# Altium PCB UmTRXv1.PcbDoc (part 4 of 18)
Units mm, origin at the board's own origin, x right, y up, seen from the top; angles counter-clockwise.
Board outline 172 x 113 mm, 6 copper layers (Top Layer, GND, MidLayer1, Mid-Layer 2, InternalPlane2, Bottom Layer); 766 components, 613 nets, 3008 pads, 1360 vias.
Unrouted connection lines stored in the file: 2.
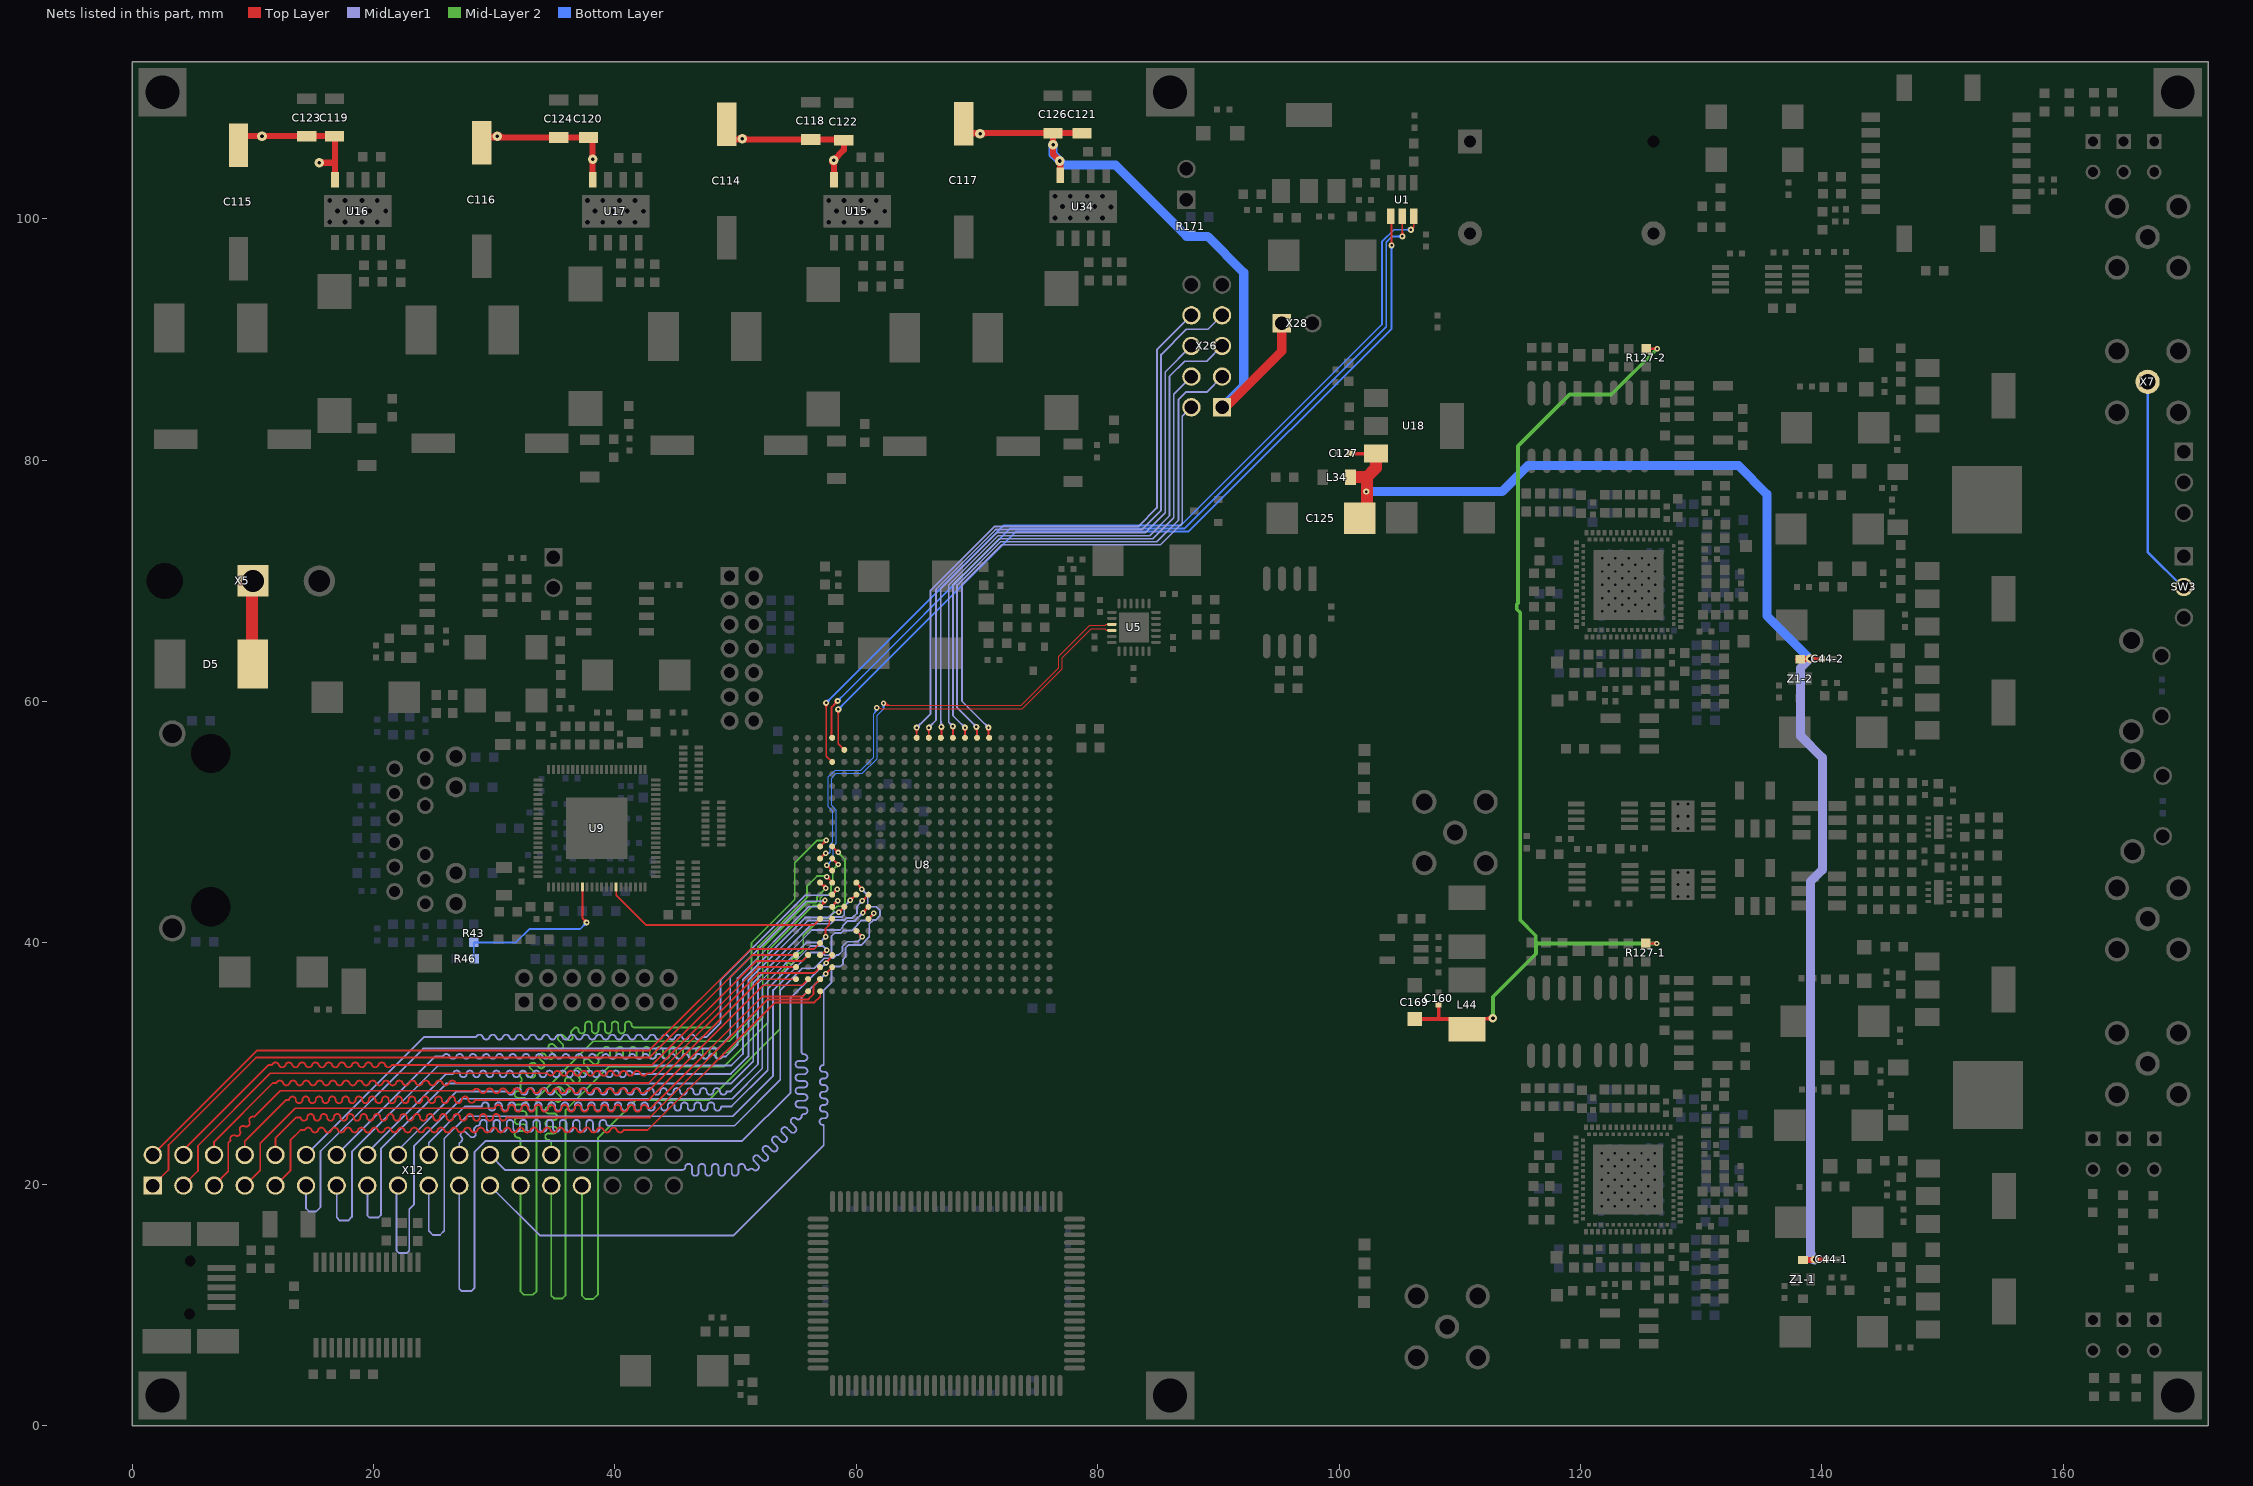
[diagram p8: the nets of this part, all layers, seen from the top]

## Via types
v1: diameter 0.45, hole 0.2, Top Layer to Bottom Layer, tented both sides, 554 vias
v2: diameter 0.5, hole 0.2, Top Layer to Bottom Layer, tented both sides, 468 vias
v3: diameter 0.7, hole 0.3, Top Layer to Bottom Layer, tented both sides, 206 vias
v4: diameter 0.4, hole 0.2, Top Layer to Bottom Layer, tented both sides, 82 vias
v5: diameter 0.8, hole 0.3, Top Layer to Bottom Layer, tented both sides, 16 vias
v6: diameter 0.6, hole 0.25, Top Layer to Bottom Layer, tented both sides, 16 vias
v7: diameter 0.5, hole 0.3, Top Layer to Bottom Layer, tented both sides, 8 vias
v8: diameter 0.7, hole 0.3, Top Layer to Bottom Layer, 4 vias
v9: diameter 0.6, hole 0.3, Top Layer to Bottom Layer, tented both sides, 4 vias
v10: diameter 0.5, hole 0.2, Top Layer to Bottom Layer, 2 vias

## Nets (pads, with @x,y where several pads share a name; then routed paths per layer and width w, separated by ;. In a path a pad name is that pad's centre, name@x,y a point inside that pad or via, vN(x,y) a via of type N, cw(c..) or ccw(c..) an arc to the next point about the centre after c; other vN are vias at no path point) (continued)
+6.5V: C44-1.1 C44-2.1 C125.1 C127.1 L34.2 U18.3 Z1-1.1 Z1-2.1 | length 118
  Top Layer w0.3: C127.1@100.9,80.6 100.95,80.55 U18.3@103.05,80.55 ; v3(139.015,63.567) 139.931,63.567 C44-2.1@139.94,63.576 ; v3@139.157,63.426 cw(c139.498,63.084) 139.498,63.567 cw(c139.498,64.05) v3@139.157,63.708 ; v3(139.415,13.772) 140.331,13.772 C44-1.1@140.34,13.781 ; v3@139.557,13.63 cw(c139.898,13.289) 139.898,13.772 cw(c139.898,14.254) v3@139.557,13.913
  Top Layer w0.5: U18.3@102.95,80.45 U18.3@103.05,80.55 ; Z1-2.1@138.04,63.526 138.975,63.526 v3(139.015,63.567) ; Z1-1.1@138.44,13.731 139.375,13.731 v3(139.415,13.772)
  Top Layer w1: L34.2@100.95,78.6 102.3,78.6 ; C125.1@101.7,75.2 102.3,75.8 102.3,78.6 ; U18.3@103.05,80.55 103.05,79.35 102.3,78.6
  MidLayer1 w0.75: v3(139.015,63.567) 138.25,62.802 138.25,57.15 140.05,55.35 140.05,46.066 139.05,45.066 139.05,14.137 ; 139.05,14.593 ccw(c140.237,14.593) v3@139.398,13.754 ; v3@139.414,13.747 cw(c139.441,14.137) 139.05,14.137 ; v3(139.415,13.772) 139.05,14.137
  Bottom Layer w0.75: v2(102.25,77.4) 113.5,77.4 115.65,79.55 133.1,79.55 135.45,77.2 135.45,67.132 v3(139.015,63.567)
+12V: C114.1 C115.1 C116.1 C117.1 C118.1 C119.1 C120.1 C121.1 C122.1 C123.1 C124.1 C126.1 D5.2 R171.1 U15.8 U16.8 U17.8 U34.8 X5.1 X26.1 X28.1 | length 102.4
  Top Layer w0.5: C115.1@9.55,106.85 v5(10.75,106.85) C123.1@14.45,106.85 C119.1@16.75,106.85 16.795,106.805 16.795,104.55 ; v5(15.5,104.65) 16.695,104.65 16.795,104.55 ; U16.8@16.795,103.305 16.795,104.55 ; C116.1@29.4,106.75 C120.1@37.8,106.75 ; C116.1@29.646,106.75 ccw(c29.646,107.454) v5@30.144,106.956 ; v5@30.356,106.956 ccw(c30.854,107.454) 30.854,106.75 ; U17.8@38.153,103.239 C120.1@38.153,106.397 ; C114.1@49.582,106.568 C118.1@56.215,106.568 58.915,106.568 C122.1@58.965,106.518 58.965,105.718 v5(58.115,104.868) ; C114.1@49.99,106.568 ccw(c49.99,107.21) v5@50.444,106.756 ; v5@50.656,106.756 ccw(c51.11,107.21) 51.11,106.568 ; v5@57.965,104.718 v5(58.115,104.868) ; v5@58.009,104.762 cw(c57.709,104.462) 58.133,104.462 ; U15.8@58.133,103.289 58.133,104.85 v5(58.115,104.868) ; C117.1@69,107.1 C126.1@76.3,107.1 ; 69.767,107.1 cw(c69.767,106.567) v5@70.144,106.944 ; v5@70.356,106.944 cw(c70.733,106.567) 70.733,107.1 ; v5@76.744,104.694 cw(c76.384,104.334) 76.893,104.334 ; U34.8@76.893,103.602 76.893,104.757 v5(76.85,104.8) 76.3,105.35 v5(76.3,106.15) C126.1@76.3,107.1 ; C121.1@78.35,107.1 C126.1@76.3,107.1
  Top Layer w0.75: X26.1@90.3,84.39 90.59,84.39 95.25,89.05 X28.1@95.25,91.55
  Top Layer w1: D5.2@9.929,63.15 X5.1@9.929,70
  Bottom Layer w0.75: v5(76.3,106.15) 76.3,105.35 v5(76.85,104.8) 77.2,104.45 81.475,104.45 87.375,98.55 89.1,98.55 92.1,95.55 92.1,86.19 X26.1@90.3,84.39
  other v5: 38.15,104.95 50.55,106.65 30.25,106.85 70.25,107.05
-5V: C160.1 C169.1 L44.2 R127-1.2 R127-2.2 | length 86.6
  Top Layer w0.2: R127-1.2@125.411,39.958 126.315,39.958 v1(126.318,39.955) ; R127-2.2@125.45,89.25 126.354,89.25 v1(126.357,89.247) ; 126.008,39.958 cw(c126.008,39.645) v1@126.23,39.866 ; 126.025,39.958 ccw(c126.025,40.248) v1@126.23,40.043 ; 126.047,89.25 cw(c126.047,88.936) v1@126.269,89.158 ; 126.064,89.25 ccw(c126.064,89.54) v1@126.269,89.335
  Top Layer w0.3: C169.1@106.25,33.7 108.2,33.7 ; C160.1@108.25,34.9 108.25,33.75 108.2,33.7 ; 112.19,33.718 ccw(c112.19,34.31) v3@112.609,33.891 ; 112.344,33.718 cw(c112.344,33.344) v3@112.609,33.609 ; v3@112.75,33.7 112.732,33.718 110.55,33.718 110.532,33.7 108.2,33.7
  Mid-Layer 2 w0.3: v3@112.609,33.891 ccw(c112.267,34.233) 112.75,34.233 ccw(c113.233,34.233) v3@112.891,33.891 ; v3(112.75,33.75) 112.75,35.55 116.319,39.119 116.319,39.955 ; 116.319,40.096 116.319,39.955 ; v1(126.318,39.955) 116.319,39.955 ; v1(126.357,89.247) 122.561,85.45 119.1,85.45 114.825,81.175 114.825,68.147 114.725,68.047 114.725,67.653 115,67.378 115,41.9 116.3,40.6 116.3,39.955 116.319,39.955
ACT_LED: R43.2 R46.1 U9.50 | length 15.8
  Top Layer w0.15: U9.50@37.3,44.625 37.3,42.05 v2(37.65,41.7) ; v2@37.475,41.7 ccw(c37.053,41.7) 37.351,41.999 ccw(c37.65,42.297) v2@37.65,41.875
  Bottom Layer w0.15: R46.1@28.35,38.7 28.3,38.75 R43.2@28.3,40.05 31.8,40.05 32.9,41.15 37.1,41.15 v2(37.65,41.7) ; v2@37.475,41.7 cw(c37.053,41.7) 37.351,41.401 cw(c37.65,41.103) v2@37.65,41.525
AUX1: U8.AB6 X26.2 | length 45.2
  Top Layer w0.15: v2@70.826,57.726 cw(c70.528,57.428) 70.95,57.428 cw(c71.372,57.428) v2@71.074,57.726 ; v2(70.95,57.85) 70.95,57.05 U8.AB6@71,57
  MidLayer1 w0.15: v2@70.775,57.85 ccw(c70.353,57.85) 70.651,58.149 ccw(c70.95,58.447) v2@70.95,58.025 ; v2(70.95,57.85) 68.75,60.05 68.75,69.7 72.05,73 85.2,73 87,74.8 87,83.63 X26.2@87.76,84.39
AUX2: U8.AB7 X26.3 | length 49.6
  Top Layer w0.15: v2@69.826,57.776 cw(c69.407,57.357) 70,57.357 ; v2(69.95,57.9) 70,57.85 U8.AB7@70,57 ; 70,57.598 cw(c70.252,57.598) v2@70.074,57.776
  MidLayer1 w0.15: v2@69.775,57.9 ccw(c69.353,57.9) 69.651,58.199 ccw(c69.95,58.497) v2@69.95,58.075 ; v2(69.95,57.9) 68.35,59.5 68.35,69.654 71.946,73.25 84.9,73.25 86.7,75.05 86.7,85.05 87.3,85.65 89.02,85.65 X26.3@90.3,86.93
AUX3: U8.AB8 X26.4 | length 47.3
  Top Layer w0.15: v2@68.876,57.726 cw(c68.578,57.428) 69,57.428 cw(c69.422,57.428) v2@69.124,57.726 ; U8.AB8@69,57 v2(69,57.85)
  MidLayer1 w0.15: v2@68.825,57.85 ccw(c68.403,57.85) 68.701,58.149 ccw(c69,58.447) v2@69,58.025 ; v2(69,57.85) 68,58.85 68,69.657 71.843,73.5 84.55,73.5 86.3,75.25 86.3,85.47 X26.4@87.76,86.93
AUX4: U8.AB9 X26.5 | length 51.8
  Top Layer w0.15: v2@67.876,57.826 cw(c67.578,57.528) 68,57.528 cw(c68.422,57.528) v2@68.124,57.826 ; U8.AB9@68,57 v2(68,57.95)
  MidLayer1 w0.15: v2@67.825,57.95 ccw(c67.403,57.95) 67.701,58.249 ccw(c68,58.547) v2@68,58.125 ; v2(68,57.95) 67.65,58.3 67.65,69.661 71.739,73.75 84.3,73.75 85.95,75.4 85.95,86.95 87.2,88.2 89.03,88.2 X26.5@90.3,89.47
AUX5: U8.AB10 X26.6 | length 49.7
  Top Layer w0.15: v2@66.926,57.776 cw(c66.628,57.478) 67.05,57.478 cw(c67.472,57.478) v2@67.174,57.776 ; U8.AB10@67,57 67.05,57.05 v2(67.05,57.9)
  MidLayer1 w0.15: v2@66.926,58.024 ccw(c66.748,58.202) 67,58.202 ; 67,58.443 ccw(c67.593,58.443) v2@67.174,58.024 ; v2(67.05,57.9) 67,57.9 66.95,57.95 67,58 67,69.364 71.636,74 83.95,74 85.6,75.65 85.6,87.31 X26.6@87.76,89.47
AUX6: U8.AB11 X26.7 | length 54.5
  Top Layer w0.15: v2@65.876,57.726 cw(c65.578,57.428) 66,57.428 cw(c66.422,57.428) v2@66.124,57.726 ; U8.AB11@66,57.05 v2(66,57.85)
  MidLayer1 w0.15: v2(66,57.85) 66.6,58.45 66.6,69.318 71.532,74.25 83.65,74.25 85.25,75.85 85.25,88.75 87.35,90.85 89.14,90.85 X26.7@90.3,92.01 ; v2@66,58.025 ccw(c66,58.447) 66.299,58.149 ccw(c66.597,57.85) v2@66.175,57.85
AUX7: U8.AB12 X26.8 | length 52.7
  Top Layer w0.15: v2@64.876,57.726 cw(c64.578,57.428) 65,57.428 cw(c65.422,57.428) v2@65.124,57.726 ; U8.AB12@65,57 v2(65,57.85)
  MidLayer1 w0.15: v2(65,57.85) 66.15,59 66.15,69.221 71.429,74.5 83.35,74.5 84.9,76.05 84.9,89.15 X26.8@87.76,92.01 ; v2@65,58.025 ccw(c65,58.447) 65.299,58.149 ccw(c65.597,57.85) v2@65.175,57.85
CLK_FPGA_N: U5.9 U8.L19 | length 43.4
  Top Layer w0.1: v1@62.232,59.832 ccw(c62.552,60.152) 62.552,59.7 ; v1(62.25,59.85) 62.4,59.7 73.65,59.7 76.77,62.82 76.77,63.754 79.334,66.318 80.3,66.318 80.617,66.318 80.7,66.4 U5.9@81.175,66.4 ; v1@62.303,59.903 ccw(c62.793,60.393) 62.793,59.7 ; v1@62.374,59.974 ccw(c63.035,60.635) 63.035,59.7
  Top Layer w0.15: v1@57.55,46.3 cw(c57.55,45.938) 57.806,46.194 cw(c58.062,46.45) v1@57.7,46.45 ; v1(57.55,46.45) U8.L19@58,46
  Bottom Layer w0.1: v1(57.55,46.45) 58.1,47 58.1,48.05 58.33,48.28 58.33,51.016 57.95,51.396 57.95,53.65 58.35,54.05 60.5,54.05 61.73,55.28 61.73,58.88 62.25,59.4 v1(62.25,59.85) ; v1@57.55,46.625 ccw(c57.55,47.047) 57.849,46.749 ccw(c58.147,46.45) v1@57.725,46.45 ; v1@62.126,59.726 cw(c61.828,59.428) 62.25,59.428 cw(c62.672,59.428) v1@62.374,59.726
CLK_FPGA_P: U5.10 U8.M20 | length 41.4
  Top Layer w0.1: v1(61.7,59.5) 61.75,59.55 61.85,59.55 62.005,59.395 62.495,59.395 62.52,59.42 73.766,59.42 77.05,62.704 77.05,63.638 79.45,66.038 80.562,66.038 80.7,65.9 U5.10@81.175,65.9
  Top Layer w0.15: U8.M20@57,47 v1(57.45,47.45) ; v1@57.3,47.45 cw(c56.938,47.45) 57.194,47.194 cw(c57.45,46.938) v1@57.45,47.3
  Bottom Layer w0.1: v1(57.45,47.45) 57.75,47.45 ; v1@57.602,47.364 cw(c57.75,47.28) 57.75,47.45 ; v1@57.602,47.536 ccw(c57.75,47.62) 57.75,47.45 ; v1@61.538,59.434 cw(c61.167,59.283) 61.45,59 ; 61.557,59.107 ccw(c61.318,59.345) v1@61.63,59.472 ; v1@61.64,59.335 cw(c61.609,59.25) 61.7,59.25 ; 61.663,59.213 ccw(c61.47,59.406) v1@61.723,59.509 ; v1(61.7,59.5) 61.7,59.25 ; v1@61.76,59.335 ccw(c61.791,59.25) 61.7,59.25 ; 57.75,47.45 57.82,47.52 57.82,48.166 58.05,48.396 58.05,50.9 57.67,51.28 57.67,53.766 58.152,54.248 58.234,54.33 60.384,54.33 61.45,55.396 61.45,59 ; 61.45,59 61.7,59.25
CLK_TO_MAC: U8.G20 U9.57 | length 18.8
  Top Layer w0.15: U9.57@40.1,44.625 40.1,43.95 42.55,41.5 56.5,41.5 U8.G20@57,42
CLKIO: SW3.2 X7.1 | length 18.3
  Bottom Layer w0.2: X7.1@167,86.5 167,72.4 SW3.2@169.95,69.45
DAC_CLK: U1.5 U8.AB19 | length 74.4
  Top Layer w0.15: U8.AB19@57.95,57 57.95,59.55 v2(58.45,60.05) ; v2@58.275,60.05 cw(c57.853,60.05) 58.151,59.751 cw(c58.45,59.453) v2@58.45,59.875 ; v2@105.126,98.674 ccw(c104.855,98.945) 105.239,98.945 ; 105.239,99 ccw(c105.7,99) v2@105.374,98.674 ; U1.5@105.239,100.215 105.239,98.561 v2(105.25,98.55)
  Bottom Layer w0.15: v2(58.45,60.05) 72.75,74.35 87.2,74.35 103.9,91.05 103.9,98.05 104.4,98.55 v2(105.25,98.55) ; v2@58.45,60.225 ccw(c58.45,60.647) 58.749,60.349 ccw(c59.047,60.05) v2@58.625,60.05 ; v2@105.126,98.426 ccw(c104.828,98.128) 104.828,98.55 ccw(c104.828,98.972) v2@105.126,98.674
DAC_DIN: U1.4 U8.AA18 | length 74.5
  Top Layer w0.15: v2@58.376,59.226 cw(c58.078,58.928) 58.5,58.928 cw(c58.922,58.928) v2@58.624,59.226 ; v2(58.5,59.35) 58.5,56.5 U8.AA18@59,56 ; v2@104.226,97.924 ccw(c103.928,98.222) 104.35,98.222 ccw(c104.772,98.222) v2@104.474,97.924 ; U1.4@104.288,100.215 104.35,100.153 v2(104.35,97.8)
  Bottom Layer w0.15: v2(58.5,59.35) 73.25,74.1 87.55,74.1 104.35,90.9 v2(104.35,97.8) ; v2@58.5,59.525 ccw(c58.5,59.947) 58.799,59.649 ccw(c59.097,59.35) v2@58.675,59.35 ; v2@104.226,97.676 cw(c103.928,97.378) 104.35,97.378 cw(c104.772,97.378) v2@104.474,97.676
DAC_NSY: U1.6 U8.Y19 | length 77.5
  Top Layer w0.15: v2@57.376,59.776 cw(c57.078,59.478) 57.5,59.478 cw(c57.922,59.478) v2@57.624,59.776 ; v2(57.5,59.9) 57.5,55.488 U8.Y19@57.994,54.994 ; v2(105.95,99.1) 106.19,99.34 ; v2@105.979,99.273 ccw(c106.019,99.51) 106.19,99.34 ; v2@106.123,99.129 cw(c106.36,99.169) 106.19,99.34 ; U1.6@106.19,100.215 106.19,99.34
  Bottom Layer w0.15: v2(57.5,59.9) 72.2,74.6 86.9,74.6 103.55,91.25 103.55,98.1 104.55,99.1 v2(105.95,99.1) ; v2@57.5,60.075 ccw(c57.5,60.497) 57.799,60.199 ccw(c58.097,59.9) v2@57.675,59.9 ; v2@105.826,98.976 ccw(c105.528,98.678) 105.528,99.1 ccw(c105.528,99.522) v2@105.826,99.224
DEBUG0: U8.D22 X12.1 | length 62.4
  Top Layer w0.15: X12.1@1.7,19.9 3,21.2 3,23.25 10.25,30.5 42.85,30.5 51.35,39 U8.D22@55,39
DEBUG1: U8.E20 X12.2 | length 62.6
  Top Layer w0.15: X12.2@1.7,22.44 10.36,31.1 42.85,31.1 51.25,39.5 56.5,39.5 U8.E20@57,40
DEBUG2: U8.C22 X12.3 | length 62.1
  Top Layer w0.15: X12.3@4.24,19.9 5.45,21.11 5.45,23.2 11.45,29.2 34.4,29.2 ccw(c34.675,29.327) 34.95,29.2 cw(c35.225,29.111) 35.5,29.2 ccw(c35.775,29.289) 36.05,29.2 cw(c36.325,29.111) 36.6,29.2 ccw(c36.875,29.289) 37.15,29.2 cw(c37.425,29.111) 37.7,29.2 ccw(c37.975,29.289) 38.25,29.2 cw(c38.525,29.111) 38.8,29.2 ccw(c39.075,29.289) 39.35,29.2 cw(c39.625,29.111) 39.9,29.2 ccw(c40.175,29.289) 40.45,29.2 cw(c40.725,29.111) 41,29.2 ccw(c41.275,29.289) 41.55,29.2 cw(c41.825,29.111) 42.1,29.2 ccw(c42.375,29.289) 42.65,29.2 43.05,29.2 51.85,38 U8.C22@55,38
DEBUG3: U8.D21 X12.4 | length 62
  Top Layer w0.15: X12.4@4.24,22.44 4.24,22.84 11.3,29.9 11.6,29.9 cw(c11.875,29.811) 12.15,29.9 ccw(c12.425,29.989) 12.7,29.9 cw(c12.975,29.811) 13.25,29.9 ccw(c13.525,29.989) 13.8,29.9 cw(c14.075,29.811) 14.35,29.9 ccw(c14.625,29.989) 14.9,29.9 cw(c15.175,29.811) 15.45,29.9 ccw(c15.725,29.989) 16,29.9 cw(c16.275,29.811) 16.55,29.9 ccw(c16.825,29.989) 17.1,29.9 cw(c17.375,29.811) 17.65,29.9 ccw(c17.925,29.989) 18.2,29.9 cw(c18.475,29.811) 18.75,29.9 ccw(c19.025,29.989) 19.3,29.9 cw(c19.575,29.811) 19.85,29.9 ccw(c20.125,29.989) 20.4,29.9 cw(c20.675,29.811) 20.95,29.9 ccw(c21.225,29.989) 21.5,29.9 43.1,29.9 51.7,38.5 55.5,38.5 U8.D21@56,39
DEBUG4: U8.B22 X12.5 | length 62.1
  Top Layer w0.15: X12.5@6.78,19.9 7.95,21.07 7.95,23.45 8.15,23.65 cw(c8.407,23.781) 8.539,24.039 ccw(c8.67,24.296) 8.928,24.428 cw(c9.185,24.559) 9.317,24.817 ccw(c9.448,25.074) 9.706,25.206 cw(c9.989,25.312) 10.095,25.595 12.25,27.75 28.25,27.75 cw(c28.525,27.607) 28.8,27.75 ccw(c29.075,27.839) 29.35,27.75 cw(c29.625,27.661) 29.9,27.75 ccw(c30.175,27.839) 30.45,27.75 cw(c30.725,27.661) 31,27.75 ccw(c31.275,27.839) 31.55,27.75 cw(c31.825,27.661) 32.1,27.75 ccw(c32.375,27.839) 32.65,27.75 cw(c32.925,27.661) 33.2,27.75 ccw(c33.475,27.839) 33.75,27.75 cw(c34.025,27.661) 34.3,27.75 ccw(c34.575,27.839) 34.85,27.75 cw(c35.125,27.661) 35.4,27.75 ccw(c35.675,27.839) 35.95,27.75 cw(c36.225,27.661) 36.5,27.75 ccw(c36.775,27.839) 37.05,27.75 cw(c37.325,27.661) 37.6,27.75 ccw(c37.875,27.839) 38.15,27.75 cw(c38.425,27.661) 38.7,27.75 ccw(c38.975,27.839) 39.25,27.75 cw(c39.525,27.661) 39.8,27.75 ccw(c40.075,27.839) 40.35,27.75 cw(c40.625,27.661) 40.9,27.75 ccw(c41.175,27.839) 41.45,27.75 cw(c41.725,27.661) 42,27.75 ccw(c42.275,27.839) 42.55,27.75 42.8,27.75 52.05,37 U8.B22@55,37
DEBUG5: U8.C20 X12.6 | length 62.1
  Top Layer w0.15: X12.6@6.78,22.44 6.78,23.53 11.65,28.4 11.95,28.4 cw(c12.225,28.311) 12.5,28.4 ccw(c12.775,28.489) 13.05,28.4 cw(c13.325,28.311) 13.6,28.4 ccw(c13.875,28.489) 14.15,28.4 cw(c14.425,28.311) 14.7,28.4 ccw(c14.975,28.489) 15.25,28.4 cw(c15.525,28.311) 15.8,28.4 ccw(c16.075,28.489) 16.35,28.4 cw(c16.625,28.311) 16.9,28.4 ccw(c17.175,28.489) 17.45,28.4 cw(c17.725,28.311) 18,28.4 ccw(c18.275,28.489) 18.55,28.4 cw(c18.825,28.311) 19.1,28.4 ccw(c19.375,28.489) 19.65,28.4 cw(c19.925,28.311) 20.2,28.4 ccw(c20.475,28.489) 20.75,28.4 cw(c21.025,28.311) 21.3,28.4 ccw(c21.575,28.489) 21.85,28.4 cw(c22.125,28.311) 22.4,28.4 ccw(c22.675,28.489) 22.95,28.4 cw(c23.225,28.311) 23.5,28.4 ccw(c23.775,28.489) 24.05,28.4 cw(c24.325,28.311) 24.6,28.4 ccw(c24.875,28.489) 25.15,28.4 cw(c25.425,28.311) 25.7,28.4 ccw(c25.975,28.489) 26.25,28.4 cw(c26.525,28.311) 26.8,28.4 42.8,28.4 51.9,37.5 56.5,37.5 U8.C20@57,38
DEBUG6: U8.A21 X12.7 | length 61.9
  Top Layer w0.15: X12.7@9.32,19.9 10.6,21.18 10.6,23.4 13.5,26.3 30.05,26.3 cw(c30.325,26.3) 30.6,26.3 ccw(c30.875,26.3) 31.15,26.3 cw(c31.425,26.3) 31.7,26.3 ccw(c31.975,26.3) 32.25,26.3 cw(c32.525,26.3) 32.8,26.3 ccw(c33.075,26.3) 33.35,26.3 cw(c33.625,26.3) 33.9,26.3 ccw(c34.175,26.3) 34.45,26.3 cw(c34.725,26.3) 35,26.3 ccw(c35.275,26.3) 35.55,26.3 cw(c35.825,26.3) 36.1,26.3 ccw(c36.375,26.3) 36.65,26.3 cw(c36.925,26.3) 37.2,26.3 ccw(c37.475,26.3) 37.75,26.3 cw(c38.025,26.3) 38.3,26.3 ccw(c38.575,26.3) 38.85,26.3 cw(c39.125,26.3) 39.4,26.3 ccw(c39.675,26.3) 39.95,26.3 cw(c40.225,26.3) 40.5,26.3 ccw(c40.775,26.3) 41.05,26.3 cw(c41.325,26.3) 41.6,26.3 ccw(c41.875,26.3) 42.15,26.3 cw(c42.425,26.3) 42.7,26.3 42.95,26.3 52.225,35.575 55.575,35.575 U8.A21@56,36
DEBUG7: U8.B21 X12.8 | length 62.1
  Top Layer w0.15: X12.8@9.32,22.44 9.32,23.57 12.75,27 13,27 cw(c13.275,27) 13.55,27 ccw(c13.825,27) 14.1,27 cw(c14.375,27) 14.65,27 ccw(c14.925,27) 15.2,27 cw(c15.475,27) 15.75,27 ccw(c16.025,27) 16.3,27 cw(c16.575,27) 16.85,27 ccw(c17.125,27) 17.4,27 cw(c17.675,27) 17.95,27 ccw(c18.225,27) 18.5,27 cw(c18.775,27) 19.05,27 ccw(c19.325,27) 19.6,27 cw(c19.875,27) 20.15,27 ccw(c20.425,27) 20.7,27 cw(c20.975,27) 21.25,27 ccw(c21.525,27) 21.8,27 cw(c22.075,27) 22.35,27 ccw(c22.625,27) 22.9,27 cw(c23.175,27) 23.45,27 ccw(c23.725,27) 24,27 cw(c24.275,27) 24.55,27 ccw(c24.825,27) 25.1,27 cw(c25.375,27) 25.65,27 ccw(c25.925,27) 26.2,27 cw(c26.475,27) 26.75,27 ccw(c27.025,27) 27.3,27 cw(c27.575,27) 27.85,27 ccw(c28.125,27.035) 28.4,27 42.8,27 52.3,36.5 55.5,36.5 U8.B21@56,37
DEBUG8: U8.A20 X12.9 | length 62
  Top Layer w0.15: X12.9@11.86,19.9 13.1,21.14 13.1,23.65 13.95,24.5 14.3,24.5 cw(c14.575,24.411) 14.85,24.5 ccw(c15.125,24.589) 15.4,24.5 cw(c15.675,24.411) 15.95,24.5 ccw(c16.225,24.589) 16.5,24.5 cw(c16.775,24.411) 17.05,24.5 ccw(c17.325,24.589) 17.6,24.5 cw(c17.875,24.411) 18.15,24.5 ccw(c18.425,24.589) 18.7,24.5 cw(c18.975,24.411) 19.25,24.5 ccw(c19.525,24.589) 19.8,24.5 cw(c20.075,24.411) 20.35,24.5 ccw(c20.625,24.589) 20.9,24.5 cw(c21.175,24.411) 21.45,24.5 ccw(c21.725,24.589) 22,24.5 cw(c22.275,24.411) 22.55,24.5 ccw(c22.825,24.589) 23.1,24.5 cw(c23.375,24.411) 23.65,24.5 ccw(c23.925,24.589) 24.2,24.5 cw(c24.475,24.411) 24.75,24.5 ccw(c25.025,24.589) 25.3,24.5 cw(c25.575,24.411) 25.85,24.5 ccw(c26.125,24.589) 26.4,24.5 cw(c26.675,24.411) 26.95,24.5 ccw(c27.225,24.589) 27.5,24.5 cw(c27.775,24.411) 28.05,24.5 ccw(c28.325,24.589) 28.6,24.5 cw(c28.875,24.411) 29.15,24.5 ccw(c29.425,24.589) 29.7,24.5 cw(c29.975,24.411) 30.25,24.5 ccw(c30.525,24.589) 30.8,24.5 cw(c31.075,24.411) 31.35,24.5 ccw(c31.625,24.589) 31.9,24.5 cw(c32.175,24.411) 32.45,24.5 ccw(c32.725,24.589) 33,24.5 cw(c33.275,24.411) 33.55,24.5 ccw(c33.825,24.589) 34.1,24.5 cw(c34.375,24.411) 34.65,24.5 ccw(c34.925,24.589) 35.2,24.5 cw(c35.475,24.411) 35.75,24.5 ccw(c36.025,24.589) 36.3,24.5 cw(c36.575,24.411) 36.85,24.5 ccw(c37.125,24.589) 37.4,24.5 cw(c37.675,24.411) 37.95,24.5 ccw(c38.225,24.589) 38.5,24.5 cw(c38.775,24.411) 39.05,24.5 ccw(c39.325,24.589) 39.6,24.5 cw(c39.875,24.411) 40.15,24.5 ccw(c40.425,24.589) 40.7,24.5 42.7,24.5 53.275,35.075 56.525,35.075 57,35.55 U8.A20@57,36
DEBUG9: U8.B20 X12.10 | length 62.1
  Top Layer w0.15: X12.10@11.86,22.44 11.86,23.81 13.6,25.55 13.95,25.55 ccw(c14.225,25.55) 14.5,25.55 cw(c14.775,25.55) 15.05,25.55 ccw(c15.325,25.55) 15.6,25.55 cw(c15.875,25.55) 16.15,25.55 ccw(c16.425,25.55) 16.7,25.55 cw(c16.975,25.55) 17.25,25.55 ccw(c17.525,25.55) 17.8,25.55 cw(c18.075,25.55) 18.35,25.55 ccw(c18.625,25.55) 18.9,25.55 cw(c19.175,25.55) 19.45,25.55 ccw(c19.725,25.55) 20,25.55 cw(c20.275,25.55) 20.55,25.55 ccw(c20.825,25.55) 21.1,25.55 cw(c21.375,25.55) 21.65,25.55 ccw(c21.925,25.55) 22.2,25.55 cw(c22.475,25.55) 22.75,25.55 ccw(c23.025,25.55) 23.3,25.55 cw(c23.575,25.55) 23.85,25.55 ccw(c24.125,25.55) 24.4,25.55 cw(c24.675,25.55) 24.95,25.55 ccw(c25.225,25.55) 25.5,25.55 cw(c25.775,25.55) 26.05,25.55 ccw(c26.325,25.55) 26.6,25.55 cw(c26.875,25.55) 27.15,25.55 ccw(c27.425,25.55) 27.7,25.55 cw(c27.975,25.55) 28.25,25.55 ccw(c28.525,25.55) 28.8,25.55 cw(c29.075,25.55) 29.35,25.55 ccw(c29.625,25.55) 29.9,25.55 cw(c30.175,25.55) 30.45,25.55 ccw(c30.725,25.558) 31,25.55 42.9,25.55 52.675,35.325 56.025,35.325 56.449,35.749 56.449,36.449 U8.B20@57,37
DEBUG10: U8.H20 X12.11 | length 63.2
  Top Layer w0.15: U8.H20@57,43 57.4,43.4 57.4,43.549 v1(57.403,43.552) ; U8.H20@57.109,43.109 ccw(c56.767,43.45) v1@57.25,43.45 ; 57.229,43.229 cw(c57.4,43.059) 57.4,43.3
  MidLayer1 w0.15: X12.11@14.4,19.9 14.4,18 14.65,17.75 15.25,17.75 15.6,18.1 15.6,22.75 24.1,31.25 48.5,31.25 49.55,32.3 49.55,37.15 55.85,43.45 57.4,43.45 57.403,43.453 v1(57.403,43.552) ; 57.294,43.344 ccw(c57.038,43.088) 57.038,43.45 ccw(c57.038,43.812) v1@57.294,43.556
DEBUG11: U8.J19 X12.12 | length 63.1
  Top Layer w0.15: U8.J19@58,44 58.4,44.4 v1(58.4,44.45) v1@58.276,44.326 ; U8.J19@58.109,44.109 ccw(c57.767,44.45) v1@58.25,44.45 ; 58.229,44.229 cw(c58.4,44.058) v1@58.4,44.3
  MidLayer1 w0.15: X12.12@14.4,22.44 24.16,32.2 28.5,32.2 cw(c28.775,32.111) 29.05,32.2 ccw(c29.325,32.289) 29.6,32.2 cw(c29.875,32.111) 30.15,32.2 ccw(c30.425,32.289) 30.7,32.2 cw(c30.975,32.111) 31.25,32.2 ccw(c31.525,32.289) 31.8,32.2 cw(c32.075,32.111) 32.35,32.2 ccw(c32.625,32.289) 32.9,32.2 cw(c33.175,32.111) 33.45,32.2 ccw(c33.725,32.289) 34,32.2 cw(c34.275,32.111) 34.55,32.2 ccw(c34.825,32.289) 35.1,32.2 cw(c35.375,32.111) 35.65,32.2 ccw(c35.925,32.289) 36.2,32.2 cw(c36.475,32.111) 36.75,32.2 ccw(c37.025,32.289) 37.3,32.2 cw(c37.575,32.111) 37.85,32.2 ccw(c38.125,32.289) 38.4,32.2 cw(c38.675,32.111) 38.95,32.2 ccw(c39.225,32.289) 39.5,32.2 cw(c39.775,32.111) 40.05,32.2 ccw(c40.325,32.289) 40.6,32.2 cw(c40.875,32.111) 41.15,32.2 ccw(c41.425,32.289) 41.7,32.2 cw(c41.975,32.111) 42.25,32.2 ccw(c42.525,32.289) 42.8,32.2 cw(c43.075,32.111) 43.35,32.2 ccw(c43.625,32.289) 43.9,32.2 cw(c44.175,32.111) 44.45,32.2 ccw(c44.725,32.289) 45,32.2 cw(c45.275,32.111) 45.55,32.2 ccw(c45.825,32.289) 46.1,32.2 cw(c46.375,32.111) 46.65,32.2 ccw(c46.925,32.289) 47.2,32.2 47.55,32.2 48.75,33.4 48.75,36.95 55.752,43.952 57.902,43.952 v1(58.4,44.45) ; v1@58.25,44.45 cw(c57.888,44.45) 58.144,44.194 cw(c58.4,43.938) v1@58.4,44.3
DEBUG12: U8.H18 X12.13 | length 62.9
  Top Layer w0.15: v1(58.55,42.55) U8.H18@59,43 ; v1@58.55,42.7 ccw(c58.55,43.062) 58.806,42.806 ccw(c59.062,42.55) v1@58.7,42.55
  MidLayer1 w0.15: X12.13@16.94,19.9 16.94,17.26 17.2,17 17.9,17 18.2,17.3 18.2,22.7 25.35,29.85 49.65,29.85 50.6,30.8 50.6,36.95 55.75,42.1 57.666,42.1 58.116,42.55 v1(58.55,42.55)
DEBUG13: U8.H19 X12.14 | length 62.7
  Top Layer w0.15: U8.H19@57.95,43.05 58.4,43.5 v1(58.45,43.5) ; U8.H19@58.109,43.209 cw(c58.45,42.867) v1@58.45,43.35 ; 58.229,43.329 ccw(c58.059,43.5) v1@58.3,43.5
  MidLayer1 w0.15: X12.14@16.94,22.44 25.1,30.6 25.75,30.6 cw(c26.025,30.511) 26.3,30.6 ccw(c26.575,30.689) 26.85,30.6 cw(c27.125,30.511) 27.4,30.6 ccw(c27.675,30.689) 27.95,30.6 cw(c28.225,30.511) 28.5,30.6 ccw(c28.775,30.689) 29.05,30.6 cw(c29.325,30.511) 29.6,30.6 ccw(c29.875,30.689) 30.15,30.6 cw(c30.425,30.511) 30.7,30.6 ccw(c30.975,30.689) 31.25,30.6 cw(c31.525,30.511) 31.8,30.6 ccw(c32.075,30.689) 32.35,30.6 cw(c32.625,30.511) 32.9,30.6 ccw(c33.175,30.689) 33.45,30.6 cw(c33.725,30.511) 34,30.6 ccw(c34.275,30.689) 34.55,30.6 cw(c34.825,30.511) 35.1,30.6 ccw(c35.375,30.689) 35.65,30.6 cw(c35.925,30.511) 36.2,30.6 ccw(c36.475,30.689) 36.75,30.6 cw(c37.025,30.511) 37.3,30.6 ccw(c37.575,30.689) 37.85,30.6 cw(c38.125,30.511) 38.4,30.6 ccw(c38.675,30.689) 38.95,30.6 cw(c39.225,30.511) 39.5,30.6 ccw(c39.775,30.689) 40.05,30.6 cw(c40.325,30.511) 40.6,30.6 ccw(c40.875,30.689) 41.15,30.6 cw(c41.425,30.511) 41.7,30.6 ccw(c41.975,30.689) 42.25,30.6 cw(c42.525,30.511) 42.8,30.6 ccw(c43.075,30.689) 43.35,30.6 cw(c43.625,30.511) 43.9,30.6 ccw(c44.175,30.689) 44.45,30.6 cw(c44.725,30.511) 45,30.6 ccw(c45.275,30.689) 45.55,30.6 cw(c45.825,30.511) 46.1,30.6 ccw(c46.375,30.689) 46.65,30.6 cw(c46.925,30.511) 47.2,30.6 ccw(c47.475,30.689) 47.75,30.6 cw(c48.025,30.511) 48.3,30.6 ccw(c48.575,30.689) 48.85,30.6 49.2,30.6 50.15,31.55 50.15,37.1 56.05,43 57.95,43 v1(58.45,43.5) ; v1@58.3,43.5 cw(c57.938,43.5) 58.194,43.244 cw(c58.45,42.988) v1@58.45,43.35
DEBUG14: U8.J16 X12.15 | length 65.2
  Top Layer w0.15: v1(60.5,43.5) 60.699,43.699 ; v1@60.5,43.65 ccw(c60.5,44.012) 60.756,43.756 ccw(c61.012,43.5) v1@60.65,43.5 ; U8.J16@61,44 60.699,43.699 ; v1@60.529,43.647 ccw(c60.565,43.834) 60.699,43.699 ; v1@60.529,43.647 ccw(c60.565,43.834) 60.699,43.699 ; v1@60.529,43.647 ccw(c60.565,43.834) 60.699,43.699 ; v1@60.529,43.647 ccw(c60.565,43.834) 60.699,43.699 ; v1@60.647,43.529 cw(c60.834,43.565) 60.699,43.699 ; v1@60.647,43.529 cw(c60.834,43.565) 60.699,43.699 ; v1@60.647,43.529 cw(c60.834,43.565) 60.699,43.699 ; v1@60.647,43.529 cw(c60.834,43.565) 60.699,43.699
  MidLayer1 w0.15: X12.15@19.48,19.9 19.48,17.42 19.65,17.25 20.4,17.25 20.6,17.45 20.6,22.95 26,28.35 49.6,28.35 51.45,30.2 51.45,36.7 56.35,41.6 57.873,41.6 58.173,41.9 59.006,41.9 59.181,42.075 59.676,42.075 60.05,42.449 60.05,43.05 v1(60.5,43.5) ; v1@60.35,43.5 cw(c59.988,43.5) 60.244,43.244 cw(c60.5,42.988) v1@60.5,43.35
DEBUG15: U8.J17 X12.16 | length 63.2
  Top Layer w0.15: v1(59.5,43.55) 59.55,43.55 U8.J17@60,44 ; v1@59.5,43.7 ccw(c59.5,44.183) U8.J17@59.841,43.841 ; v1@59.65,43.55 cw(c59.891,43.55) 59.721,43.721
  MidLayer1 w0.15: X12.16@19.48,22.44 19.48,22.63 26,29.15 26.6,29.15 cw(c26.875,29.15) 27.15,29.15 ccw(c27.425,29.15) 27.7,29.15 cw(c27.975,29.15) 28.25,29.15 ccw(c28.525,29.15) 28.8,29.15 cw(c29.075,29.15) 29.35,29.15 ccw(c29.625,29.15) 29.9,29.15 cw(c30.175,29.15) 30.45,29.15 ccw(c30.725,29.15) 31,29.15 cw(c31.275,29.15) 31.55,29.15 ccw(c31.825,29.15) 32.1,29.15 cw(c32.375,29.15) 32.65,29.15 ccw(c32.925,29.15) 33.2,29.15 cw(c33.475,29.15) 33.75,29.15 ccw(c34.025,29.15) 34.3,29.15 cw(c34.575,29.15) 34.85,29.15 ccw(c35.125,29.15) 35.4,29.15 cw(c35.675,29.15) 35.95,29.15 ccw(c36.225,29.15) 36.5,29.15 cw(c36.775,29.15) 37.05,29.15 ccw(c37.325,29.15) 37.6,29.15 cw(c37.875,29.15) 38.15,29.15 ccw(c38.425,29.15) 38.7,29.15 cw(c38.975,29.15) 39.25,29.15 ccw(c39.525,29.15) 39.8,29.15 cw(c40.075,29.15) 40.35,29.15 ccw(c40.625,29.15) 40.9,29.15 cw(c41.175,29.127) 41.45,29.15 49.6,29.15 51.05,30.6 51.05,36.907 55.993,41.85 57.769,41.85 58.069,42.15 58.8,42.15 59,42.35 59,43.05 v1(59.5,43.55) ; v1@59.35,43.55 cw(c58.988,43.55) 59.244,43.294 cw(c59.5,43.038) v1@59.5,43.4
DEBUG16: U8.G19 X12.17 | length 63.7
  Top Layer w0.15: v1@57.344,40.606 ccw(c57.088,40.862) 57.45,40.862 ccw(c57.812,40.862) v1@57.556,40.606 ; v1(57.45,40.5) 57.45,41.196 57.75,41.496 57.75,41.8 U8.G19@57.975,42.025
  MidLayer1 w0.15: X12.17@22.02,19.9 21.9,19.9 21.9,14.5 22.1,14.3 22.75,14.3 22.95,14.5 22.95,17.95 23.35,18.35 23.35,23.2 27.25,27.1 49.7,27.1 52.2,29.6 52.2,36.35 55.9,40.05 57,40.05 v1(57.45,40.5) ; v1@57.3,40.5 cw(c56.938,40.5) 57.194,40.244 cw(c57.45,39.988) v1@57.45,40.35
DEBUG17: U8.H16 X12.18 | length 63.2
  Top Layer w0.15: v1(60.55,42.5) 60.55,42.55 U8.H16@61,43 ; v1@60.55,42.65 ccw(c60.55,42.891) 60.721,42.721 ; v1@60.7,42.5 cw(c61.183,42.5) U8.H16@60.841,42.841
  MidLayer1 w0.15: X12.18@22.02,22.44 22.02,22.82 26.9,27.7 31.1,27.7 ccw(c31.375,27.7) 31.65,27.7 cw(c31.925,27.7) 32.2,27.7 ccw(c32.475,27.7) 32.75,27.7 cw(c33.025,27.7) 33.3,27.7 ccw(c33.575,27.7) 33.85,27.7 cw(c34.125,27.7) 34.4,27.7 ccw(c34.675,27.7) 34.95,27.7 cw(c35.225,27.7) 35.5,27.7 ccw(c35.775,27.7) 36.05,27.7 cw(c36.325,27.7) 36.6,27.7 ccw(c36.875,27.7) 37.15,27.7 cw(c37.425,27.7) 37.7,27.7 ccw(c37.975,27.7) 38.25,27.7 cw(c38.525,27.7) 38.8,27.7 ccw(c39.075,27.7) 39.35,27.7 cw(c39.625,27.7) 39.9,27.7 ccw(c40.175,27.7) 40.45,27.7 cw(c40.725,27.7) 41,27.7 ccw(c41.275,27.7) 41.55,27.7 cw(c41.825,27.7) 42.1,27.7 ccw(c42.375,27.7) 42.65,27.7 cw(c42.925,27.7) 43.2,27.7 ccw(c43.475,27.7) 43.75,27.7 cw(c44.025,27.7) 44.3,27.7 ccw(c44.575,27.7) 44.85,27.7 cw(c45.125,27.7) 45.4,27.7 ccw(c45.675,27.7) 45.95,27.7 cw(c46.225,27.7) 46.5,27.7 ccw(c46.775,27.7) 47.05,27.7 cw(c47.325,27.7) 47.6,27.7 ccw(c47.875,27.7) 48.15,27.7 cw(c48.425,27.7) 48.7,27.7 ccw(c48.975,27.7) 49.25,27.7 49.6,27.7 51.85,29.95 51.85,36.6 56.327,41.077 58.644,41.077 58.878,41.311 58.878,41.419 59.284,41.825 59.875,41.825 v1(60.55,42.5) ; v1@60.4,42.5 cw(c60.038,42.5) 60.294,42.244 cw(c60.55,41.988) v1@60.55,42.35
DEBUG18: U8.G16 X12.19 | length 63.3
  Top Layer w0.15: U8.G16@61,42 61.301,42.301 v1(61.45,42.45) ; v1@61.3,42.45 cw(c60.938,42.45) 61.194,42.194 cw(c61.45,41.938) v1@61.45,42.3
  MidLayer1 w0.15: X12.19@24.56,19.9 24.56,16.14 24.9,15.8 25.5,15.8 25.85,16.15 25.85,23.8 27.7,25.65 49.75,25.65 53.1,29 53.1,36.1 56.2,39.2 57.174,39.2 57.384,38.989 57.716,38.989 57.95,39.224 57.95,40.575 58.202,40.827 58.747,40.827 58.945,41.025 59.616,41.025 60.1,41.509 60.1,41.566 60.384,41.85 60.9,41.85 61.45,42.4 v1(61.45,42.45) ; 61.159,42.109 ccw(c60.817,42.45) v1@61.3,42.45 ; 61.279,42.229 cw(c61.45,42.059) v1@61.45,42.3
DEBUG19: U8.D20 X12.20 | length 63
  Top Layer w0.15: U8.D20@57.05,38.95 57.489,39.389 v1(57.55,39.389) ; U8.D20@57.19,39.09 cw(c57.55,38.731) v1@57.55,39.239 ; 57.337,39.237 ccw(c57.184,39.389) v1@57.4,39.389
  MidLayer1 w0.15: X12.20@24.56,22.44 24.56,23.46 27.55,26.45 28.9,26.45 ccw(c28.9,26.525) 28.975,26.521 ; 57.251,39.749 cw(c56.891,39.389) v1@57.4,39.389 ; 57.397,39.603 ccw(c57.55,39.755) v1@57.55,39.539 ; v1(57.55,39.389) 57.55,39.45 57.25,39.75 56.2,39.75 52.65,36.2 52.65,29.45 49.65,26.45 48.85,26.45 ccw(c48.85,26.375) 48.775,26.375 cw(c48.5,26.375) 48.5,26.1 cw(c48.5,26.375) 48.225,26.375 48.225,26.52 ccw(c47.95,26.52) 47.95,26.795 ccw(c47.95,26.52) 47.675,26.52 47.675,26.38 cw(c47.4,26.38) 47.4,26.105 cw(c47.4,26.38) 47.125,26.38 47.125,26.52 ccw(c46.85,26.52) 46.85,26.795 ccw(c46.85,26.52) 46.575,26.52 46.575,26.38 cw(c46.3,26.38) 46.3,26.105 cw(c46.3,26.38) 46.025,26.38 46.025,26.52 ccw(c45.75,26.52) 45.75,26.795 ccw(c45.75,26.52) 45.475,26.52 45.475,26.38 cw(c45.2,26.38) 45.2,26.105 cw(c45.2,26.38) 44.925,26.38 44.925,26.52 ccw(c44.65,26.52) 44.65,26.795 ccw(c44.65,26.52) 44.375,26.52 44.375,26.38 cw(c44.1,26.38) 44.1,26.105 cw(c44.1,26.38) 43.825,26.38 43.825,26.52 ccw(c43.55,26.52) 43.55,26.795 ccw(c43.55,26.52) 43.275,26.52 43.275,26.38 cw(c43,26.38) 43,26.105 cw(c43,26.38) 42.725,26.38 42.725,26.52 ccw(c42.45,26.52) 42.45,26.795 ccw(c42.45,26.52) 42.175,26.52 42.175,26.38 cw(c41.9,26.38) 41.9,26.105 cw(c41.9,26.38) 41.625,26.38 41.625,26.52 ccw(c41.35,26.52) 41.35,26.795 ccw(c41.35,26.52) 41.075,26.52 41.075,26.38 cw(c40.8,26.38) 40.8,26.105 cw(c40.8,26.38) 40.525,26.38 40.525,26.52 ccw(c40.25,26.52) 40.25,26.795 ccw(c40.25,26.52) 39.975,26.52 39.975,26.38 cw(c39.7,26.38) 39.7,26.105 cw(c39.7,26.38) 39.425,26.38 39.425,26.52 ccw(c39.15,26.52) 39.15,26.795 ccw(c39.15,26.52) 38.875,26.52 38.875,26.38 cw(c38.6,26.38) 38.6,26.105 cw(c38.6,26.38) 38.325,26.38 38.325,26.52 ccw(c38.05,26.52) 38.05,26.795 ccw(c38.05,26.52) 37.775,26.52 37.775,26.38 cw(c37.5,26.38) 37.5,26.105 cw(c37.5,26.38) 37.225,26.38 37.225,26.52 ccw(c36.95,26.52) 36.95,26.795 ccw(c36.95,26.52) 36.675,26.52 36.675,26.38 cw(c36.4,26.38) 36.4,26.105 cw(c36.4,26.38) 36.125,26.38 36.125,26.52 ccw(c35.85,26.52) 35.85,26.795 ccw(c35.85,26.52) 35.575,26.52 35.575,26.38 cw(c35.3,26.38) 35.3,26.105 cw(c35.3,26.38) 35.025,26.38 35.025,26.52 ccw(c34.75,26.52) 34.75,26.795 ccw(c34.75,26.52) 34.475,26.52 34.475,26.38 cw(c34.2,26.38) 34.2,26.105 cw(c34.2,26.38) 33.925,26.38 33.925,26.52 ccw(c33.65,26.52) 33.65,26.795 ccw(c33.65,26.52) 33.375,26.52 33.375,26.38 cw(c33.1,26.38) 33.1,26.105 cw(c33.1,26.38) 32.825,26.38 32.825,26.52 ccw(c32.55,26.52) 32.55,26.795 ccw(c32.55,26.52) 32.275,26.52 32.275,26.38 cw(c32,26.38) 32,26.105 cw(c32,26.38) 31.725,26.38 31.725,26.52 ccw(c31.45,26.52) 31.45,26.795 ccw(c31.45,26.52) 31.175,26.52 31.175,26.38 cw(c30.9,26.38) 30.9,26.105 cw(c30.9,26.38) 30.625,26.38 30.625,26.52 ccw(c30.35,26.52) 30.35,26.795 ccw(c30.35,26.52) 30.075,26.52 30.075,26.38 cw(c29.8,26.38) 29.8,26.105 cw(c29.8,26.38) 29.525,26.38 29.525,26.52 ccw(c29.25,26.52) 29.25,26.795 ccw(c29.25,26.52) 28.975,26.525 ; 28.975,26.521 cw(c29.25,26.52) 28.975,26.525 ; 28.975,26.521 ccw(c28.9,26.525) 28.975,26.525 ; 28.975,26.521 28.975,26.525
DEBUG20: U8.D19 X12.21 | length 63.7
  Top Layer w0.15: v1(57.5,38.339) 57.5,38.4 U8.D19@58.05,38.95 ; v1@57.5,38.489 ccw(c57.5,38.705) 57.653,38.553 ; v1@57.65,38.339 cw(c58.159,38.339) 57.799,38.699
  MidLayer1 w0.15: X12.21@27.1,19.9 27.1,11.35 27.3,11.15 28.1,11.15 28.35,11.4 28.35,22.65 29.3,23.6 50.55,23.6 54.55,27.6 54.55,35.45 57.55,38.45 57.55,38.389 v1(57.5,38.339) ; 57.14,38.04 cw(c57.5,37.681) v1@57.5,38.189 ; 57.287,38.187 ccw(c57.134,38.339) v1@57.35,38.339
DEBUG21: U8.F17 X12.22 | length 63.5
  Top Layer w0.15: U8.F17@60,41 60.301,40.699 ; v1@60.35,40.5 ccw(c59.988,40.5) 60.244,40.756 ccw(c60.5,41.012) v1@60.5,40.65 ; v1(60.5,40.5) 60.301,40.699 ; 60.301,40.699 ccw(c60.435,40.834) 60.471,40.647 cw(c60.435,40.834) 60.301,40.699 ; 60.301,40.699 cw(c60.166,40.565) 60.353,40.529 ccw(c60.166,40.565) 60.301,40.699
  MidLayer1 w0.15: X12.22@27.1,22.44 27.1,23.4 27.285,23.585 ccw(c27.126,23.744) 27.285,23.904 cw(c27.48,24.098) 27.285,24.292 cw(c27.48,24.098) 27.674,24.293 27.988,23.979 ccw(c28.182,24.174) 28.376,23.979 ccw(c28.182,24.174) 28.38,24.364 ; v1(60.5,40.5) 60.1,40.1 59.225,40.1 58.85,39.725 58.85,39.334 58.516,39 58.35,39 58.089,38.739 57.334,38.739 56.925,38.33 56.925,38.324 56.501,37.9 55.5,37.9 53.7,36.1 53.7,28.65 49.9,24.85 39.5,24.85 cw(c39.5,25.075) 39.275,25.069 ; 28.377,24.367 cw(c28.54,24.522) 28.381,24.681 28.55,24.85 28.6,24.85 ccw(c28.6,25.075) 28.825,25.075 cw(c29.1,25.075) 29.1,25.35 cw(c29.1,25.075) 29.375,25.075 29.375,24.632 ccw(c29.65,24.632) 29.65,24.357 ccw(c29.65,24.632) 29.925,24.632 29.925,25.068 cw(c30.2,25.068) 30.2,25.343 cw(c30.2,25.068) 30.475,25.068 30.475,24.632 ccw(c30.75,24.632) 30.75,24.357 ccw(c30.75,24.632) 31.025,24.632 31.025,25.068 cw(c31.3,25.068) 31.3,25.343 cw(c31.3,25.068) 31.575,25.068 31.575,24.632 ccw(c31.85,24.632) 31.85,24.357 ccw(c31.85,24.632) 32.125,24.632 32.125,25.068 cw(c32.4,25.068) 32.4,25.343 cw(c32.4,25.068) 32.675,25.068 32.675,24.632 ccw(c32.95,24.632) 32.95,24.357 ccw(c32.95,24.632) 33.225,24.632 33.225,25.068 cw(c33.5,25.068) 33.5,25.343 cw(c33.5,25.068) 33.775,25.068 33.775,24.632 ccw(c34.05,24.632) 34.05,24.357 ccw(c34.05,24.632) 34.325,24.632 34.325,25.068 cw(c34.6,25.068) 34.6,25.343 cw(c34.6,25.068) 34.875,25.068 34.875,24.632 ccw(c35.15,24.632) 35.15,24.357 ccw(c35.15,24.632) 35.425,24.632 35.425,25.068 cw(c35.7,25.068) 35.7,25.343 cw(c35.7,25.068) 35.975,25.068 35.975,24.632 ccw(c36.25,24.632) 36.25,24.357 ccw(c36.25,24.632) 36.525,24.632 36.525,25.068 cw(c36.8,25.068) 36.8,25.343 cw(c36.8,25.068) 37.075,25.068 37.075,24.632 ccw(c37.35,24.632) 37.35,24.357 ccw(c37.35,24.632) 37.625,24.632 37.625,25.068 cw(c37.9,25.068) 37.9,25.343 cw(c37.9,25.068) 38.175,25.068 38.175,24.632 ccw(c38.45,24.632) 38.45,24.357 ccw(c38.45,24.632) 38.725,24.632 38.725,25.068 cw(c39,25.068) 39,25.343 cw(c39,25.068) 39.275,25.074 ; 28.377,24.367 ccw(c28.54,24.522) 28.381,24.364 ; 28.377,24.367 cw(c28.182,24.174) 28.38,24.364 ; 28.377,24.367 28.381,24.364 ; 39.275,25.069 cw(c39.5,25.075) 39.275,25.074 ; 39.275,25.069 ccw(c39,25.068) 39.275,25.074 ; 39.275,25.069 39.275,25.074
DEBUG22: U8.K17 X12.23 | length 63
  Top Layer w0.15: U8.K17@60,45 60.45,44.55 v1(60.45,44.45) ; U8.K17@60.123,44.877 cw(c59.696,44.45) v1@60.3,44.45
  MidLayer1 w0.15: X12.23@29.64,19.9 33.79,15.75 49.8,15.75 57.3,23.25 57.3,24.85 ccw(c57.225,24.85) 57.225,24.925 cw(c57.225,25.2) 56.95,25.2 cw(c57.225,25.2) 57.225,25.475 57.348,25.475 ccw(c57.348,25.75) 57.623,25.75 ccw(c57.348,25.75) 57.348,26.025 57.252,26.025 cw(c57.252,26.3) 56.977,26.3 cw(c57.252,26.3) 57.252,26.575 57.348,26.575 ccw(c57.348,26.85) 57.623,26.85 ccw(c57.348,26.85) 57.348,27.125 57.252,27.125 cw(c57.252,27.4) 56.977,27.4 cw(c57.252,27.4) 57.252,27.675 57.348,27.675 ccw(c57.348,27.95) 57.623,27.95 ccw(c57.348,27.95) 57.348,28.225 57.252,28.225 cw(c57.252,28.5) 56.977,28.5 cw(c57.252,28.5) 57.252,28.775 57.348,28.775 ccw(c57.348,29.05) 57.623,29.05 ccw(c57.348,29.05) 57.348,29.325 57.252,29.325 cw(c57.252,29.6) 56.977,29.6 cw(c57.252,29.6) 57.252,29.875 ; 57.225,29.875 ccw(c57.225,29.95) 57.3,29.95 57.3,36.1 57.95,36.75 57.95,37.8 58.2,38.05 58.334,38.05 58.666,38.05 58.9,38.284 58.9,38.65 59.1,38.85 59.1,39.6 59.325,39.825 60.391,39.825 61.075,40.509 61.075,41.591 61.384,41.9 61.6,41.9 61.95,42.25 61.95,42.7 61.65,43 61.15,43 60.95,43.2 60.95,43.95 v1(60.45,44.45) ; 57.23,29.875 57.247,29.875 ; v1@60.45,44.3 cw(c60.45,43.938) 60.706,44.194 cw(c60.962,44.45) v1@60.6,44.45
DEBUG23: U8.C19 X12.24 | length 63.2
  Top Layer w0.15: v1(57.45,37.45) U8.C19@58,38 ; v1@57.45,37.6 ccw(c57.45,37.962) 57.706,37.706 ccw(c57.962,37.45) v1@57.6,37.45
  MidLayer1 w0.15: X12.24@29.64,22.44 30.88,21.2 45.6,21.2 ccw(c45.6,21.425) 45.825,21.425 cw(c46.1,21.425) 46.1,21.7 cw(c46.1,21.425) 46.375,21.425 46.375,20.983 ccw(c46.65,20.983) 46.65,20.708 ccw(c46.65,20.983) 46.925,20.983 46.925,21.417 cw(c47.2,21.417) 47.2,21.692 cw(c47.2,21.417) 47.475,21.417 47.475,20.983 ccw(c47.75,20.983) 47.75,20.708 ccw(c47.75,20.983) 48.025,20.983 48.025,21.417 cw(c48.3,21.417) 48.3,21.692 cw(c48.3,21.417) 48.575,21.417 48.575,20.983 ccw(c48.85,20.983) 48.85,20.708 ccw(c48.85,20.983) 49.125,20.983 49.125,21.417 cw(c49.4,21.417) 49.4,21.692 cw(c49.4,21.417) 49.675,21.417 49.675,20.983 ccw(c49.95,20.983) 49.95,20.708 ccw(c49.95,20.983) 50.225,20.983 50.225,21.417 cw(c50.5,21.417) 50.5,21.692 cw(c50.5,21.417) 50.775,21.424 ; 50.775,21.417 ccw(c50.5,21.417) 50.775,21.419 ; 50.775,21.425 ccw(c51,21.425) 50.775,21.424 ; 51.529,21.937 cw(c51.724,22.132) 51.53,22.326 cw(c51.724,22.132) 51.918,22.326 52.226,22.019 ccw(c52.42,22.213) 52.615,22.019 ccw(c52.42,22.213) 52.615,22.407 52.307,22.715 cw(c52.502,22.909) 52.307,23.104 cw(c52.502,22.909) 52.696,23.104 52.85,22.95 53.004,22.796 ; 51.53,21.937 51.842,21.624 cw(c51.648,21.43) 51.842,21.235 cw(c51.648,21.43) 51.454,21.235 ccw(c51.294,21.076) 51.135,21.235 51.1,21.2 51,21.2 cw(c51,21.425) 50.775,21.419 ; 53.004,22.796 ccw(c53.198,22.991) 53.393,22.796 ccw(c53.198,22.991) 53.393,23.185 53.239,23.339 53.085,23.493 ; 53.085,23.493 cw(c53.28,23.687) 53.085,23.882 cw(c53.28,23.687) 53.474,23.882 53.628,23.728 53.782,23.574 ; 53.782,23.574 ccw(c53.976,23.769) 54.171,23.574 ccw(c53.976,23.769) 54.171,23.963 54.017,24.117 53.863,24.271 cw(c54.058,24.465) 53.863,24.659 cw(c54.058,24.465) 54.252,24.66 54.406,24.506 54.559,24.352 ccw(c54.754,24.546) 54.948,24.352 ccw(c54.754,24.546) 54.949,24.741 54.795,24.895 54.641,25.048 cw(c54.835,25.243) 54.641,25.437 cw(c54.835,25.243) 55.025,25.442 ; 55.024,25.443 ccw(c55.184,25.602) 55.025,25.442 ; 55.03,25.437 ccw(c54.835,25.243) 55.029,25.438 ; 55.667,30.775 cw(c55.667,30.5) 55.669,30.775 ; 55.675,30.775 cw(c55.675,31) 55.674,30.775 ; v1@57.3,37.45 cw(c56.938,37.45) 57.194,37.194 cw(c57.45,36.938) v1@57.45,37.3 ; v1(57.45,37.45) 55.45,35.45 55.45,31 ccw(c55.675,31) 55.669,30.775 ; 50.775,21.419 cw(c51,21.425) 50.775,21.424 ; 50.775,21.419 ccw(c50.5,21.417) 50.775,21.424 ; 50.775,21.419 50.775,21.424 ; 55.025,25.442 ccw(c55.184,25.602) 55.029,25.438 ; 55.025,25.442 cw(c54.835,25.243) 55.029,25.438 ; 55.025,25.442 55.029,25.438 ; 55.029,25.438 ccw(c55.184,25.602) 55.343,25.443 55.45,25.55 55.45,25.6 cw(c55.675,25.6) 55.675,25.825 ccw(c55.675,26.1) 55.95,26.1 ccw(c55.675,26.1) 55.675,26.375 55.233,26.375 cw(c55.233,26.65) 54.958,26.65 cw(c55.233,26.65) 55.233,26.925 55.667,26.925 ccw(c55.667,27.2) 55.942,27.2 ccw(c55.667,27.2) 55.667,27.475 55.233,27.475 cw(c55.233,27.75) 54.958,27.75 cw(c55.233,27.75) 55.233,28.025 55.667,28.025 ccw(c55.667,28.3) 55.942,28.3 ccw(c55.667,28.3) 55.667,28.575 55.233,28.575 cw(c55.233,28.85) 54.958,28.85 cw(c55.233,28.85) 55.233,29.125 55.667,29.125 ccw(c55.667,29.4) 55.942,29.4 ccw(c55.667,29.4) 55.667,29.675 55.233,29.675 cw(c55.233,29.95) 54.958,29.95 cw(c55.233,29.95) 55.233,30.225 55.667,30.225 ccw(c55.667,30.5) 55.942,30.5 ccw(c55.667,30.5) 55.674,30.775 ccw(c55.667,30.5) 55.669,30.775 ; 55.669,30.775 ccw(c55.675,31) 55.674,30.775 ; 55.669,30.775 55.674,30.775
DEBUG24: U8.K19 X12.25 | length 63.6
  Top Layer w0.15: v1@57.55,45.35 cw(c57.55,44.988) 57.806,45.244 cw(c58.062,45.5) v1@57.7,45.5 ; v1@57.55,45.55 v1(57.55,45.5) U8.K19@58,45.05
  Mid-Layer 2 w0.15: X12.25@32.18,19.9 32.18,11.12 32.45,10.85 33.2,10.85 33.5,11.15 33.5,27.15 38.2,31.85 49.45,31.85 51.85,34.25 51.85,39.7 55.9,43.75 55.9,44.7 56.75,45.55 57.5,45.55 v1(57.55,45.5) ; 57.067,45.55 cw(c57.067,45.017) v1@57.444,45.394 ; 57.309,45.55 ccw(c57.309,45.741) v1@57.444,45.606
DEBUG25: U8.N20 X12.26 | length 63.7
  Top Layer w0.15: U8.N20@57.05,48.05 v1(57.5,48.5) ; v1@57.35,48.5 cw(c56.988,48.5) 57.244,48.244 cw(c57.5,47.988) v1@57.5,48.35
  Mid-Layer 2 w0.15: 31.955,27.725 ccw(c31.955,27.95) 31.956,27.725 ; 31.962,27.725 ccw(c31.962,27.45) 31.96,27.725 ; X12.26@32.18,22.44 32.18,23.65 ccw(c31.955,23.65) 31.955,23.875 cw(c31.955,24.15) 31.68,24.15 cw(c31.955,24.15) 31.955,24.425 32.398,24.425 ccw(c32.398,24.7) 32.673,24.7 ccw(c32.398,24.7) 32.398,24.975 31.962,24.975 cw(c31.962,25.25) 31.687,25.25 cw(c31.962,25.25) 31.962,25.525 32.398,25.525 ccw(c32.398,25.8) 32.673,25.8 ccw(c32.398,25.8) 32.398,26.075 31.962,26.075 cw(c31.962,26.35) 31.687,26.35 cw(c31.962,26.35) 31.962,26.625 32.398,26.625 ccw(c32.398,26.9) 32.673,26.9 ccw(c32.398,26.9) 32.398,27.175 31.962,27.175 cw(c31.962,27.45) 31.687,27.45 cw(c31.962,27.45) 31.956,27.725 ; 34.553,31.163 cw(c34.748,31.357) 34.553,31.551 cw(c34.748,31.357) 34.942,31.551 35.097,31.397 35.251,31.242 ; 34.553,31.162 34.708,31.008 34.862,30.853 cw(c34.668,30.659) 34.862,30.465 cw(c34.668,30.659) 34.474,30.464 34.319,30.619 34.165,30.773 ccw(c33.97,30.579) 33.776,30.773 ccw(c33.97,30.579) 33.775,30.385 33.93,30.23 34.085,30.076 cw(c33.89,29.881) 34.085,29.687 cw(c33.89,29.881) 33.696,29.687 33.387,29.996 ccw(c33.192,29.801) 32.998,29.996 ccw(c33.192,29.801) 32.998,29.607 33.307,29.298 cw(c33.112,29.103) 33.307,28.909 cw(c33.112,29.103) 32.918,28.909 32.604,29.222 ccw(c32.41,29.028) 32.215,29.222 ccw(c32.41,29.028) 32.215,28.834 cw(c32.056,28.674) 32.215,28.515 32.18,28.48 32.18,27.95 cw(c31.955,27.95) 31.96,27.725 ; 35.251,31.242 ccw(c35.446,31.437) 35.64,31.242 ccw(c35.446,31.437) 35.64,31.631 35.486,31.786 35.331,31.94 cw(c35.526,32.135) 35.331,32.329 cw(c35.526,32.135) 35.72,32.329 35.875,32.175 36.029,32.02 ccw(c36.224,32.215) 36.418,32.02 ccw(c36.224,32.215) 36.422,32.405 ; 36.418,32.409 cw(c36.224,32.215) 36.419,32.408 ; 41.375,33.218 ccw(c41.1,33.218) 41.375,33.22 ; 41.375,33.225 ccw(c41.6,33.225) 41.375,33.224 ; v1@57.394,48.394 ccw(c57.138,48.138) 57.138,48.5 ccw(c57.138,48.862) v1@57.394,48.606 ; v1(57.5,48.5) 56.75,48.5 54.9,46.65 54.9,43.6 51.3,40 51.3,36.2 48.1,33 41.6,33 cw(c41.6,33.225) 41.375,33.22 ; 31.956,27.725 cw(c31.962,27.45) 31.96,27.725 ; 31.956,27.725 ccw(c31.955,27.95) 31.96,27.725 ; 31.956,27.725 31.96,27.725 ; 36.419,32.408 cw(c36.582,32.564) 36.423,32.723 36.7,33 36.75,33 cw(c36.75,32.775) 36.975,32.775 ccw(c37.25,32.775) 37.25,32.5 ccw(c37.25,32.775) 37.525,32.775 37.525,33.218 cw(c37.8,33.218) 37.8,33.493 cw(c37.8,33.218) 38.075,33.218 38.075,32.782 ccw(c38.35,32.782) 38.35,32.507 ccw(c38.35,32.782) 38.625,32.782 38.625,33.218 cw(c38.9,33.218) 38.9,33.493 cw(c38.9,33.218) 39.175,33.218 39.175,32.782 ccw(c39.45,32.782) 39.45,32.507 ccw(c39.45,32.782) 39.725,32.782 39.725,33.218 cw(c40,33.218) 40,33.493 cw(c40,33.218) 40.275,33.218 40.275,32.782 ccw(c40.55,32.782) 40.55,32.507 ccw(c40.55,32.782) 40.825,32.782 40.825,33.218 cw(c41.1,33.218) 41.1,33.493 cw(c41.1,33.218) 41.375,33.224 ; 36.419,32.408 ccw(c36.582,32.564) 36.422,32.405 ; 36.419,32.408 cw(c36.224,32.215) 36.422,32.405 ; 36.419,32.408 36.422,32.405 ; 36.422,32.405 ccw(c36.582,32.564) 36.423,32.404 ; 41.375,33.22 cw(c41.6,33.225) 41.375,33.224 ; 41.375,33.22 ccw(c41.1,33.218) 41.375,33.224 ; 41.375,33.22 41.375,33.224
DEBUG26: U8.M19 X12.27 | length 63.3
  Top Layer w0.15: U8.M19@58.1,46.9 v1(58.5,46.5) ; v1@58.35,46.5 ccw(c57.988,46.5) 58.244,46.756 ccw(c58.5,47.012) v1@58.5,46.65
  Mid-Layer 2 w0.15: X12.27@34.72,19.9 34.72,10.78 34.95,10.55 35.65,10.55 35.9,10.8 35.9,26.15 39.5,29.75 49,29.75 52.65,33.4 52.65,39.35 56.4,43.1 56.754,43.1 57,43.346 57,43.715 57.237,43.952 57.606,43.952 57.9,44.246 57.9,44.9 58.05,45.05 58.05,46.05 v1(58.5,46.5) ; v1@58.35,46.5 cw(c57.988,46.5) 58.244,46.244 cw(c58.5,45.988) v1@58.5,46.35
DEBUG27: U8.K20 X12.28 | length 62.9
  Top Layer w0.15: U8.K20@57,45 57.4,44.6 57.45,44.6 57.453,44.597 v1(57.453,44.527) ; U8.K20@57.109,44.891 ccw(c57.45,45.233) v1@57.45,44.75 ; 57.229,44.771 cw(c57.059,44.6) v1@57.3,44.6
  Mid-Layer 2 w0.15: 34.495,26.425 ccw(c34.495,26.65) 34.497,26.425 ; 34.505,26.425 ccw(c34.505,26.15) 34.504,26.425 ; X12.28@34.72,22.44 34.72,23.45 ccw(c34.495,23.45) 34.495,23.675 cw(c34.495,23.95) 34.22,23.95 cw(c34.495,23.95) 34.495,24.225 34.935,24.225 ccw(c34.935,24.5) 35.21,24.5 ccw(c34.935,24.5) 34.935,24.775 34.505,24.775 cw(c34.505,25.05) 34.23,25.05 cw(c34.505,25.05) 34.505,25.325 34.935,25.325 ccw(c34.935,25.6) 35.21,25.6 ccw(c34.935,25.6) 34.935,25.875 34.505,25.875 cw(c34.505,26.15) 34.23,26.15 cw(c34.505,26.15) 34.497,26.425 ; 35.151,27.605 cw(c35.346,27.8) 35.152,27.994 cw(c35.346,27.8) 35.54,27.994 35.844,27.691 ccw(c36.038,27.885) 36.233,27.691 ccw(c36.038,27.885) 36.233,28.079 35.929,28.383 cw(c36.124,28.577) 35.929,28.772 cw(c36.124,28.577) 36.318,28.772 36.47,28.62 36.622,28.468 ccw(c36.816,28.663) 37.011,28.468 ccw(c36.816,28.663) 37.011,28.857 ; 35.152,27.605 35.462,27.294 cw(c35.268,27.1) 35.462,26.905 cw(c35.268,27.1) 35.074,26.905 ccw(c34.914,26.746) 34.755,26.905 34.72,26.87 34.72,26.65 cw(c34.495,26.65) 34.504,26.425 ; 36.707,29.161 36.859,29.009 37.011,28.857 ; 36.707,29.161 cw(c36.902,29.355) 36.707,29.55 cw(c36.902,29.355) 37.096,29.55 37.248,29.398 37.4,29.246 ccw(c37.594,29.441) 37.789,29.246 ccw(c37.594,29.441) 37.789,29.635 37.637,29.787 37.485,29.939 cw(c37.68,30.133) 37.485,30.327 cw(c37.68,30.133) 37.874,30.328 38.026,30.176 38.177,30.024 ccw(c38.372,30.218) 38.566,30.024 ccw(c38.372,30.218) 38.572,30.407 ; 38.566,30.413 cw(c38.372,30.218) 38.568,30.412 ; 38.574,30.406 cw(c38.733,30.565) 38.572,30.407 ; 48.925,30.675 cw(c49.15,30.675) 48.925,30.677 ; 48.925,30.685 cw(c48.65,30.685) 48.925,30.684 ; v1(57.453,44.527) 57.453,44.597 57.45,44.6 57.45,44.519 56.75,43.819 56.75,43.45 56.65,43.35 55.943,43.35 52.25,39.657 52.25,33.8 49.35,30.9 49.15,30.9 ccw(c49.15,30.675) 48.925,30.684 ; 34.497,26.425 cw(c34.505,26.15) 34.504,26.425 ; 34.497,26.425 ccw(c34.495,26.65) 34.504,26.425 ; 34.497,26.425 34.504,26.425 ; 38.568,30.412 ccw(c38.733,30.565) 38.572,30.407 ; 38.568,30.412 cw(c38.372,30.218) 38.572,30.407 ; 38.568,30.412 cw(c38.733,30.565) 38.574,30.724 38.75,30.9 38.8,30.9 ccw(c38.8,31.125) 39.025,31.125 cw(c39.3,31.125) 39.3,31.4 cw(c39.3,31.125) 39.575,31.125 39.575,30.685 ccw(c39.85,30.685) 39.85,30.41 ccw(c39.85,30.685) 40.125,30.685 40.125,31.115 cw(c40.4,31.115) 40.4,31.39 cw(c40.4,31.115) 40.675,31.115 40.675,30.685 ccw(c40.95,30.685) 40.95,30.41 ccw(c40.95,30.685) 41.225,30.685 41.225,31.115 cw(c41.5,31.115) 41.5,31.39 cw(c41.5,31.115) 41.775,31.115 41.775,30.685 ccw(c42.05,30.685) 42.05,30.41 ccw(c42.05,30.685) 42.325,30.685 42.325,31.115 cw(c42.6,31.115) 42.6,31.39 cw(c42.6,31.115) 42.875,31.115 42.875,30.685 ccw(c43.15,30.685) 43.15,30.41 ccw(c43.15,30.685) 43.425,30.685 43.425,31.115 cw(c43.7,31.115) 43.7,31.39 cw(c43.7,31.115) 43.975,31.115 43.975,30.685 ccw(c44.25,30.685) 44.25,30.41 ccw(c44.25,30.685) 44.525,30.685 44.525,31.115 cw(c44.8,31.115) 44.8,31.39 cw(c44.8,31.115) 45.075,31.115 45.075,30.685 ccw(c45.35,30.685) 45.35,30.41 ccw(c45.35,30.685) 45.625,30.685 45.625,31.115 cw(c45.9,31.115) 45.9,31.39 cw(c45.9,31.115) 46.175,31.115 46.175,30.685 ccw(c46.45,30.685) 46.45,30.41 ccw(c46.45,30.685) 46.725,30.685 46.725,31.115 cw(c47,31.115) 47,31.39 cw(c47,31.115) 47.275,31.115 47.275,30.685 ccw(c47.55,30.685) 47.55,30.41 ccw(c47.55,30.685) 47.825,30.685 47.825,31.115 cw(c48.1,31.115) 48.1,31.39 cw(c48.1,31.115) 48.375,31.115 48.375,30.685 ccw(c48.65,30.685) 48.65,30.41 ccw(c48.65,30.685) 48.925,30.677 ; 38.568,30.412 38.572,30.407 ; 48.925,30.677 cw(c49.15,30.675) 48.925,30.684 ; 48.925,30.677 ccw(c48.65,30.685) 48.925,30.684 ; 48.925,30.677 48.925,30.684
DEBUG28: U8.N19 X12.29 | length 63.2
  Top Layer w0.15: U8.N19@57.9,48 U8.N19@58,48 v1(58.5,47.5) ; v1@58.35,47.5 ccw(c57.988,47.5) 58.244,47.756 ccw(c58.5,48.012) v1@58.5,47.65
  Mid-Layer 2 w0.15: X12.29@37.26,19.9 37.26,10.79 37.55,10.5 38.2,10.5 38.6,10.9 38.6,23.85 41.75,27 47.8,27 53.65,32.85 53.65,37.45 54.065,37.865 ccw(c54.171,37.971) 54.277,38.077 cw(c54.383,38.183) 54.489,38.289 ccw(c54.595,38.395) 54.701,38.501 cw(c54.808,38.608) 54.914,38.714 ccw(c55.02,38.82) 55.126,38.926 cw(c55.232,39.032) 55.338,39.138 55.6,39.4 55.6,40.6 57.05,42.05 57.7,42.05 58.1,42.45 58.1,42.75 58.4,43.05 58.8,43.05 59.05,43.3 59.05,46.95 v1(58.5,47.5) ; v1@58.5,47.35 cw(c58.5,46.988) 58.756,47.244 cw(c59.012,47.5) v1@58.65,47.5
